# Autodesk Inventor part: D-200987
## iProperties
Created: 2007-10
Part Number: D-200987
Document SubType Name: Modeling
Designer: TH
Density: 7.85 g/cm^3
Mass: 525.707 g
Surface Area: 188.847 cm^2
Volume: 66.969 cm^3
Material: Steel
Description: PIVOT BAR
Component Category: Lower Component
Rod_Major_Diameter: 15.000 mm
Author: TH
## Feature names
1. Revolution1
